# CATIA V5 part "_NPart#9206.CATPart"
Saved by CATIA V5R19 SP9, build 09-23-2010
Part number: 70_poupée
Revision: ANY
Definition: UNKNOWN
Nomenclature: 70_poupée
Source: Unknown
Bounding box of the stored display mesh (mm): x -264.806 to 264.806, y -165 to 210, z -265 to 265
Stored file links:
  Y:\fin de projet cabestan poupee\_NPart#9206.CATPart
  Ass_arbre poupee_1.CATProduct
  Y:\bricolage cabestan\6_axe.CATPart
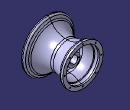
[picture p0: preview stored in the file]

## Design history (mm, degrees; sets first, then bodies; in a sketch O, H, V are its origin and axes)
Body1 "NONE" (main body)
  Solid1: solid without history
